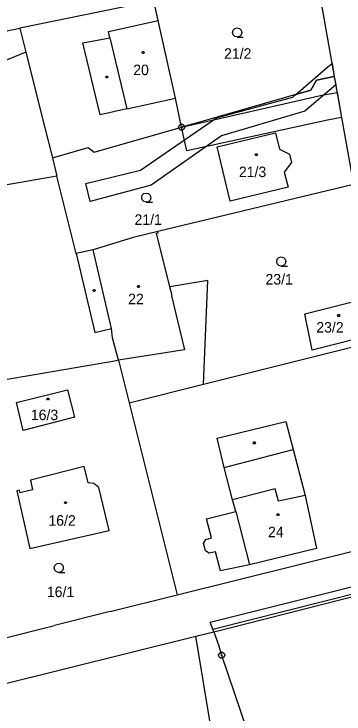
# Model space of a CAD drawing. Extents: x -759060 to -757386, y -1172273 to -1170948.
# Drawn here: x -757696.5 to -757643.1, y -1171287.4 to -1171174 of the extents above; entities that cross this region are included whole.
import ezdxf

# ---------------------------------------------------------------- set-up
doc = ezdxf.new("R2010")
doc.units = 0
for name, color, linetype in [('Vrstva 1', 7, 'Continuous'), ('Vrstva 12', 7, 'Continuous'), ('Vrstva 13', 7, 'Continuous'), ('Vrstva 2', 7, 'Continuous'), ('Vrstva 3', 7, 'Continuous'), ('Vrstva 4', 7, 'Continuous'), ('Vrstva 5', 7, 'Continuous'), ('Vrstva 8', 7, 'Continuous')]:
    doc.layers.add(name, color=color, linetype=linetype)

msp = doc.modelspace()

# ---------------------------------------------------------------- linework, layer by layer
at = {"layer": 'Vrstva 1'}
for p, q in [((-757647.8, -1171166.6), (-757644.69, -1171184.15)), ((-757673.89, -1171171.9), (-757695.6, -1171176.3)), ((-757673.22, -1171175.08), (-757673.89, -1171171.9)), ((-757670.39, -1171187.66), (-757673.22, -1171175.08)), ((-757724.26, -1171182.42), (-757695.6, -1171176.3)), ((-757695.6, -1171176.3), (-757694.62, -1171180.23)), ((-757694.62, -1171180.23), (-757724.98, -1171192.45)), ((-757694.62, -1171180.23), (-757691.56, -1171192.46)), ((-757644.69, -1171184.15), (-757647.58, -1171184.74)), ((-757644.69, -1171184.15), (-757641.56, -1171201.64)), ((-757647.58, -1171184.74), (-757648.48, -1171186.38)), ((-757648.48, -1171186.38), (-757667.04, -1171191.69)), ((-757669.41, -1171192.36), (-757670.39, -1171187.66)), ((-757667.04, -1171191.69), (-757669.41, -1171192.36)), ((-757691.56, -1171192.46), (-757690.32, -1171197.33)), ((-757683.59, -1171196.42), (-757669.41, -1171192.36)), ((-757663.66, -1171195.53), (-757654.22, -1171193.26)), ((-757654.22, -1171193.26), (-757653.56, -1171195.89)), ((-757690.32, -1171197.33), (-757684.56, -1171195.63)), ((-757684.56, -1171195.63), (-757683.59, -1171196.42)), ((-757661.56, -1171204.32), (-757663.66, -1171195.53)), ((-757653.56, -1171195.89), (-757651.95, -1171196.74)), ((-757651.95, -1171196.74), (-757651.63, -1171198.09)), ((-757690.32, -1171197.33), (-757689.6, -1171200.27)), ((-757651.63, -1171198.09), (-757652.8, -1171199.65)), ((-757689.6, -1171200.27), (-757704.81, -1171202.96)), ((-757688.58, -1171204.37), (-757689.6, -1171200.27)), ((-757652.8, -1171199.65), (-757652.16, -1171202.07)), ((-757641.56, -1171201.64), (-757673.28, -1171209.26)), ((-757652.16, -1171202.07), (-757661.56, -1171204.32)), ((-757686.46, -1171212.83), (-757688.58, -1171204.37)), ((-757673.28, -1171209.26), (-757677.27, -1171210.22)), ((-757673.23, -1171209.46), (-757673.28, -1171209.26)), ((-757677.27, -1171210.22), (-757683.75, -1171212.19)), ((-757673.49, -1171209.53), (-757673.23, -1171209.46)), ((-757671.29, -1171218.2), (-757673.49, -1171209.53)), ((-757683.75, -1171212.19), (-757686.46, -1171212.83)), ((-757680.75, -1171224.96), (-757683.75, -1171212.19)), ((-757665.19, -1171217.18), (-757671.29, -1171218.2)), ((-757665.86, -1171233.96), (-757665.19, -1171217.18)), ((-757649.47, -1171222.58), (-757640.68, -1171220.36)), ((-757648.26, -1171228.48), (-757649.47, -1171222.58)), ((-757680.61, -1171226.45), (-757680.75, -1171224.96)), ((-757639.54, -1171226.25), (-757648.26, -1171228.48)), ((-757679.63, -1171230.08), (-757680.61, -1171226.45)), ((-757665.86, -1171233.96), (-757637.09, -1171226.77)), ((-757708.3, -1171234.95), (-757679.63, -1171230.08)), ((-757679.63, -1171230.08), (-757677.91, -1171236.97)), ((-757677.91, -1171236.97), (-757665.86, -1171233.96)), ((-757696.13, -1171236.92), (-757687.87, -1171234.87)), ((-757687.87, -1171234.87), (-757686.77, -1171239.31)), ((-757695.05, -1171241.45), (-757696.13, -1171236.92)), ((-757677.91, -1171236.97), (-757670.11, -1171268.1)), ((-757686.77, -1171239.31), (-757695.05, -1171241.45)), ((-757663.67, -1171242.73), (-757652.53, -1171240.01)), ((-757652.53, -1171240.01), (-757651.37, -1171244.52)), ((-757662.51, -1171247.47), (-757663.67, -1171242.73)), ((-757651.37, -1171244.52), (-757649.42, -1171251.98)), ((-757685.19, -1171247.29), (-757693.89, -1171249.49)), ((-757684.51, -1171249.92), (-757685.19, -1171247.29)), ((-757661.18, -1171252.7), (-757662.51, -1171247.47)), ((-757693.89, -1171249.49), (-757693.53, -1171251.1)), ((-757683.64, -1171250.06), (-757684.51, -1171249.92)), ((-757682.81, -1171250.69), (-757683.64, -1171250.06)), ((-757695.65, -1171251.12), (-757696.09, -1171251.22)), ((-757696.09, -1171251.22), (-757693.98, -1171260.58)), ((-757695.55, -1171251.56), (-757695.65, -1171251.12)), ((-757693.53, -1171251.1), (-757695.55, -1171251.56)), ((-757681.12, -1171257.68), (-757682.81, -1171250.69)), ((-757649.42, -1171251.98), (-757647.58, -1171260.6)), ((-757660.66, -1171254.59), (-757661.18, -1171252.7)), ((-757665.38, -1171255.79), (-757660.66, -1171254.59)), ((-757664.55, -1171258.85), (-757665.38, -1171255.79)), ((-757664.78, -1171272.51), (-757599.66, -1171256.21)), ((-757693.98, -1171260.58), (-757681.12, -1171257.68)), ((-757664.36, -1171273.65), (-757602.54, -1171257.98)), ((-757670.11, -1171268.1), (-757631.41, -1171258.41)), ((-757665.86, -1171259.75), (-757665.51, -1171259.11)), ((-757665.51, -1171259.11), (-757664.55, -1171258.85)), ((-757661.83, -1171273.45), (-757602.71, -1171258.52)), ((-757665.56, -1171260.93), (-757665.86, -1171259.75)), ((-757664.93, -1171261.35), (-757665.56, -1171260.93)), ((-757663.94, -1171261.11), (-757664.93, -1171261.35)), ((-757663.09, -1171264.17), (-757663.94, -1171261.11)), ((-757647.58, -1171260.6), (-757658.44, -1171263.21)), ((-757658.44, -1171263.21), (-757663.09, -1171264.17)), ((-757680.96, -1171270.8), (-757670.11, -1171268.1)), ((-757680.96, -1171270.8), (-757690.01, -1171273.06)), ((-757664.36, -1171273.65), (-757664.78, -1171272.51)), ((-757706.07, -1171277.06), (-757690.01, -1171273.06)), ((-757664.22, -1171274.04), (-757664.36, -1171273.65)), ((-757664.22, -1171274.04), (-757661.83, -1171273.45)), ((-757702.86, -1171283.66), (-757667.12, -1171274.77)), ((-757667.12, -1171274.77), (-757664.22, -1171274.04)), ((-757655.25, -1171345.35), (-757667.12, -1171274.77)), ((-757664.22, -1171274.04), (-757663.38, -1171276.34)), ((-757663.38, -1171276.34), (-757662.93, -1171277.85)), ((-757662.93, -1171277.85), (-757658.33, -1171291.42))]:
    msp.add_line(p, q, dxfattribs=at)
at = {"layer": 'Vrstva 12'}
for p, q in [((-757681.24, -1171176.88), (-757673.22, -1171175.08)), ((-757670.39, -1171187.66), (-757673.22, -1171175.08)), ((-757681.01, -1171177.89), (-757681.24, -1171176.88)), ((-757681.01, -1171177.89), (-757678.26, -1171189.38)), ((-757678.26, -1171189.38), (-757670.39, -1171187.66)), ((-757663.66, -1171195.53), (-757654.22, -1171193.26)), ((-757654.22, -1171193.26), (-757653.56, -1171195.89)), ((-757661.56, -1171204.32), (-757663.66, -1171195.53)), ((-757653.56, -1171195.89), (-757651.95, -1171196.74)), ((-757651.95, -1171196.74), (-757651.63, -1171198.09)), ((-757651.63, -1171198.09), (-757652.8, -1171199.65)), ((-757652.8, -1171199.65), (-757652.16, -1171202.07)), ((-757652.16, -1171202.07), (-757661.56, -1171204.32)), ((-757673.28, -1171209.26), (-757677.27, -1171210.22)), ((-757673.23, -1171209.46), (-757673.28, -1171209.26)), ((-757677.27, -1171210.22), (-757683.75, -1171212.19)), ((-757673.49, -1171209.53), (-757673.23, -1171209.46)), ((-757671.29, -1171218.2), (-757673.49, -1171209.53)), ((-757680.75, -1171224.96), (-757683.75, -1171212.19)), ((-757670.92, -1171219.63), (-757671.29, -1171218.2)), ((-757671.03, -1171219.66), (-757670.92, -1171219.63)), ((-757671.03, -1171219.66), (-757668.93, -1171228.4)), ((-757649.47, -1171222.58), (-757640.68, -1171220.36)), ((-757648.26, -1171228.48), (-757649.47, -1171222.58)), ((-757680.61, -1171226.45), (-757680.75, -1171224.96)), ((-757639.54, -1171226.25), (-757648.26, -1171228.48)), ((-757679.63, -1171230.08), (-757680.61, -1171226.45)), ((-757668.93, -1171228.4), (-757679.63, -1171230.08)), ((-757696.13, -1171236.92), (-757687.87, -1171234.87)), ((-757687.87, -1171234.87), (-757686.77, -1171239.31)), ((-757695.05, -1171241.45), (-757696.13, -1171236.92)), ((-757686.77, -1171239.31), (-757695.05, -1171241.45)), ((-757685.19, -1171247.29), (-757693.89, -1171249.49)), ((-757684.51, -1171249.92), (-757685.19, -1171247.29)), ((-757693.89, -1171249.49), (-757693.53, -1171251.1)), ((-757683.64, -1171250.06), (-757684.51, -1171249.92)), ((-757682.81, -1171250.69), (-757683.64, -1171250.06)), ((-757695.65, -1171251.12), (-757696.09, -1171251.22)), ((-757696.09, -1171251.22), (-757693.98, -1171260.58)), ((-757695.55, -1171251.56), (-757695.65, -1171251.12)), ((-757693.53, -1171251.1), (-757695.55, -1171251.56)), ((-757681.12, -1171257.68), (-757682.81, -1171250.69)), ((-757654.24, -1171250.89), (-757661.18, -1171252.7)), ((-757653.75, -1171252.9), (-757654.24, -1171250.89)), ((-757649.42, -1171251.98), (-757653.75, -1171252.9)), ((-757649.42, -1171251.98), (-757647.58, -1171260.6)), ((-757660.66, -1171254.59), (-757661.18, -1171252.7)), ((-757660.66, -1171254.59), (-757658.44, -1171263.21)), ((-757693.98, -1171260.58), (-757681.12, -1171257.68)), ((-757647.58, -1171260.6), (-757658.44, -1171263.21))]:
    msp.add_line(p, q, dxfattribs=at)
at = {"layer": 'Vrstva 13'}
for p, q in [((-757645.72, -1171182.6), (-757645.06, -1171182.04)), ((-757645.06, -1171182.04), (-757644.69, -1171184.15)), ((-757650.93, -1171187.08), (-757645.72, -1171182.6)), ((-757647.58, -1171184.74), (-757644.69, -1171184.15)), ((-757644.69, -1171184.15), (-757647.58, -1171184.74)), ((-757644.69, -1171184.15), (-757644.45, -1171185.48)), ((-757644.45, -1171185.48), (-757649.46, -1171189.78)), ((-757648.48, -1171186.38), (-757647.58, -1171184.74)), ((-757647.58, -1171184.74), (-757648.48, -1171186.38)), ((-757650.93, -1171187.08), (-757648.48, -1171186.38)), ((-757648.48, -1171186.38), (-757650.93, -1171187.08)), ((-757669.41, -1171192.36), (-757646.69, -1171187.17)), ((-757663.78, -1171190.86), (-757651.42, -1171187.5)), ((-757651.42, -1171187.5), (-757650.93, -1171187.08)), ((-757646.69, -1171187.17), (-757644.23, -1171186.73)), ((-757644.23, -1171186.73), (-757643.51, -1171190.77)), ((-757649.46, -1171189.78), (-757662.96, -1171193.74)), ((-757676.06, -1171199.3), (-757663.78, -1171190.86)), ((-757643.51, -1171190.77), (-757645.81, -1171191.23)), ((-757645.81, -1171191.23), (-757668.55, -1171196.16)), ((-757668.55, -1171196.16), (-757669.41, -1171192.36)), ((-757662.96, -1171193.74), (-757674.36, -1171201.76)), ((-757684.93, -1171201.46), (-757676.06, -1171199.3)), ((-757684.19, -1171204.38), (-757684.93, -1171201.46)), ((-757674.36, -1171201.76), (-757684.19, -1171204.38))]:
    msp.add_line(p, q, dxfattribs=at)
at = {"layer": 'Vrstva 3'}
for points in [[(-757660.4, -1171177.75), (-757660.78, -1171177.65), (-757661.05, -1171177.38), (-757661.15, -1171177.01), (-757661.05, -1171176.64), (-757660.78, -1171176.37), (-757660.41, -1171176.27), (-757660.04, -1171176.37), (-757659.77, -1171176.64), (-757659.67, -1171177.02), (-757659.77, -1171177.4), (-757660.04, -1171177.67), (-757660.42, -1171177.77), (-757659.42, -1171177.77)], [(-757675.12, -1171204.5), (-757675.5, -1171204.4), (-757675.77, -1171204.13), (-757675.87, -1171203.76), (-757675.77, -1171203.39), (-757675.5, -1171203.12), (-757675.13, -1171203.02), (-757674.76, -1171203.12), (-757674.49, -1171203.39), (-757674.39, -1171203.77), (-757674.49, -1171204.15), (-757674.76, -1171204.42), (-757675.14, -1171204.52), (-757674.14, -1171204.52)], [(-757653.27, -1171214.85), (-757653.65, -1171214.75), (-757653.92, -1171214.48), (-757654.02, -1171214.11), (-757653.92, -1171213.74), (-757653.65, -1171213.47), (-757653.28, -1171213.37), (-757652.91, -1171213.47), (-757652.64, -1171213.74), (-757652.54, -1171214.12), (-757652.64, -1171214.5), (-757652.91, -1171214.77), (-757653.29, -1171214.87), (-757652.29, -1171214.87)], [(-757689.29, -1171264.44), (-757689.67, -1171264.34), (-757689.94, -1171264.07), (-757690.04, -1171263.7), (-757689.94, -1171263.33), (-757689.67, -1171263.06), (-757689.3, -1171262.96), (-757688.93, -1171263.06), (-757688.66, -1171263.33), (-757688.56, -1171263.71), (-757688.66, -1171264.09), (-757688.93, -1171264.36), (-757689.31, -1171264.46), (-757688.31, -1171264.46)]]:
    msp.add_lwpolyline(points, dxfattribs=at)
at = {"layer": 'Vrstva 4'}
for p, q in [((-757681.24, -1171176.88), (-757673.22, -1171175.08)), ((-757681.01, -1171177.89), (-757681.24, -1171176.88)), ((-757685.4, -1171178.69), (-757681.01, -1171177.89)), ((-757682.59, -1171190.33), (-757685.4, -1171178.69)), ((-757681.01, -1171177.89), (-757678.26, -1171189.38)), ((-757678.26, -1171189.38), (-757670.39, -1171187.66)), ((-757678.26, -1171189.38), (-757682.59, -1171190.33)), ((-757686.46, -1171212.83), (-757683.46, -1171225.6)), ((-757670.92, -1171219.63), (-757671.29, -1171218.2)), ((-757671.03, -1171219.66), (-757670.92, -1171219.63)), ((-757671.03, -1171219.66), (-757668.93, -1171228.4)), ((-757683.46, -1171225.6), (-757680.75, -1171224.96)), ((-757668.93, -1171228.4), (-757679.63, -1171230.08)), ((-757662.51, -1171247.47), (-757651.37, -1171244.52)), ((-757654.24, -1171250.89), (-757661.18, -1171252.7)), ((-757653.75, -1171252.9), (-757654.24, -1171250.89)), ((-757649.42, -1171251.98), (-757653.75, -1171252.9)), ((-757660.66, -1171254.59), (-757658.44, -1171263.21))]:
    msp.add_line(p, q, dxfattribs=at)
at = {"layer": 'Vrstva 5'}
for points in [[(-757675.54, -1171180.12), (-757675.45, -1171180.27), (-757675.54, -1171180.42), (-757675.72, -1171180.42), (-757675.81, -1171180.27), (-757675.72, -1171180.12)], [(-757681.42, -1171184.08), (-757681.33, -1171184.23), (-757681.42, -1171184.38), (-757681.6, -1171184.38), (-757681.69, -1171184.23), (-757681.6, -1171184.08)], [(-757657.23, -1171196.66), (-757657.14, -1171196.81), (-757657.23, -1171196.96), (-757657.41, -1171196.96), (-757657.5, -1171196.81), (-757657.41, -1171196.66)], [(-757676.3, -1171217.99), (-757676.21, -1171218.14), (-757676.3, -1171218.29), (-757676.48, -1171218.29), (-757676.57, -1171218.14), (-757676.48, -1171217.99)], [(-757683.47, -1171218.66), (-757683.38, -1171218.81), (-757683.47, -1171218.96), (-757683.65, -1171218.96), (-757683.74, -1171218.81), (-757683.65, -1171218.66)], [(-757643.91, -1171222.71), (-757643.82, -1171222.86), (-757643.91, -1171223.01), (-757644.09, -1171223.01), (-757644.18, -1171222.86), (-757644.09, -1171222.71)], [(-757690.94, -1171236.21), (-757690.85, -1171236.36), (-757690.94, -1171236.51), (-757691.12, -1171236.51), (-757691.21, -1171236.36), (-757691.12, -1171236.21)], [(-757657.55, -1171243.31), (-757657.46, -1171243.46), (-757657.55, -1171243.61), (-757657.73, -1171243.61), (-757657.82, -1171243.46), (-757657.73, -1171243.31)], [(-757688.11, -1171253.01), (-757688.02, -1171253.16), (-757688.11, -1171253.31), (-757688.29, -1171253.31), (-757688.38, -1171253.16), (-757688.29, -1171253.01)], [(-757653.7, -1171254.94), (-757653.61, -1171255.09), (-757653.7, -1171255.24), (-757653.88, -1171255.24), (-757653.97, -1171255.09), (-757653.88, -1171254.94)]]:
    msp.add_lwpolyline(points, close=True, dxfattribs=at)
at = {"layer": 'Vrstva 8'}
for p, q in [((-757669.53, -1171192.36), (-757669.29, -1171192.36)), ((-757663.05, -1171277.85), (-757662.81, -1171277.85))]:
    msp.add_line(p, q, dxfattribs=at)
for points in [[(-757669.26, -1171191.88), (-757669.01, -1171192.06), (-757668.91, -1171192.35), (-757669.01, -1171192.64), (-757669.26, -1171192.82), (-757669.57, -1171192.82), (-757669.82, -1171192.64), (-757669.92, -1171192.35), (-757669.82, -1171192.06), (-757669.57, -1171191.88)], [(-757662.78, -1171277.37), (-757662.53, -1171277.55), (-757662.43, -1171277.84), (-757662.53, -1171278.13), (-757662.78, -1171278.31), (-757663.09, -1171278.31), (-757663.34, -1171278.13), (-757663.44, -1171277.84), (-757663.34, -1171277.55), (-757663.09, -1171277.37)]]:
    msp.add_lwpolyline(points, close=True, dxfattribs=at)

# ---------------------------------------------------------------- texts
at = {"layer": 'Vrstva 2'}
for s, p in [('21/2', (-757662.533, -1171181.28)), ('20', (-757677.245, -1171183.93)), ('21/3', (-757660.137, -1171200.44)), ('21/1', (-757677.031, -1171208.17)), ('23/1', (-757655.827, -1171217.83)), ('22', (-757678.072, -1171221.02)), ('23/2', (-757647.608, -1171225.61)), ('16/3', (-757693.813, -1171239.79)), ('16/2', (-757690.969, -1171256.88)), ('24', (-757655.419, -1171258.74)), ('16/1', (-757691.218, -1171268.44))]:
    msp.add_text(s, height=1.7, dxfattribs=at).set_placement(p)

doc.saveas('drawing.dxf')
